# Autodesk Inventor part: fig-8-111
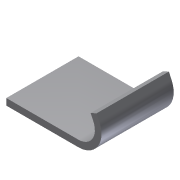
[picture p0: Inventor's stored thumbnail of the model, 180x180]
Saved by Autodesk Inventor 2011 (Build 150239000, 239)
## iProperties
Created: 2009-09
Part Number: fig-8-111
Document SubType Name: Modeling
Designer: Sham
Density: 1 g/cm^3
Author: Sham
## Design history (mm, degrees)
sketch "Sketch1"
  geometry: L1 (-33.976, 22)-(0, 22); L2 (0, 22)-(0, 0); L3 (0, 0)-(-33.976, 0); L4 (-33.976, 0)-(-33.976, 22)
  constraints: 8 end point, 2 parallel, 1 horizontal, 1 perpendicular
extrude "Extrusion1" new body sketch "Sketch1" distance "d0" = 2; taper "d1" = 0 deg
sketch "Sketch2"
  geometry: L1 (-12, 22)-(-12, 0)
  constraints: 2 end point
feature "Bend Part1" sketch "Sketch2" dims "d2" = 5, "d4" = 10
body "Solid1"
